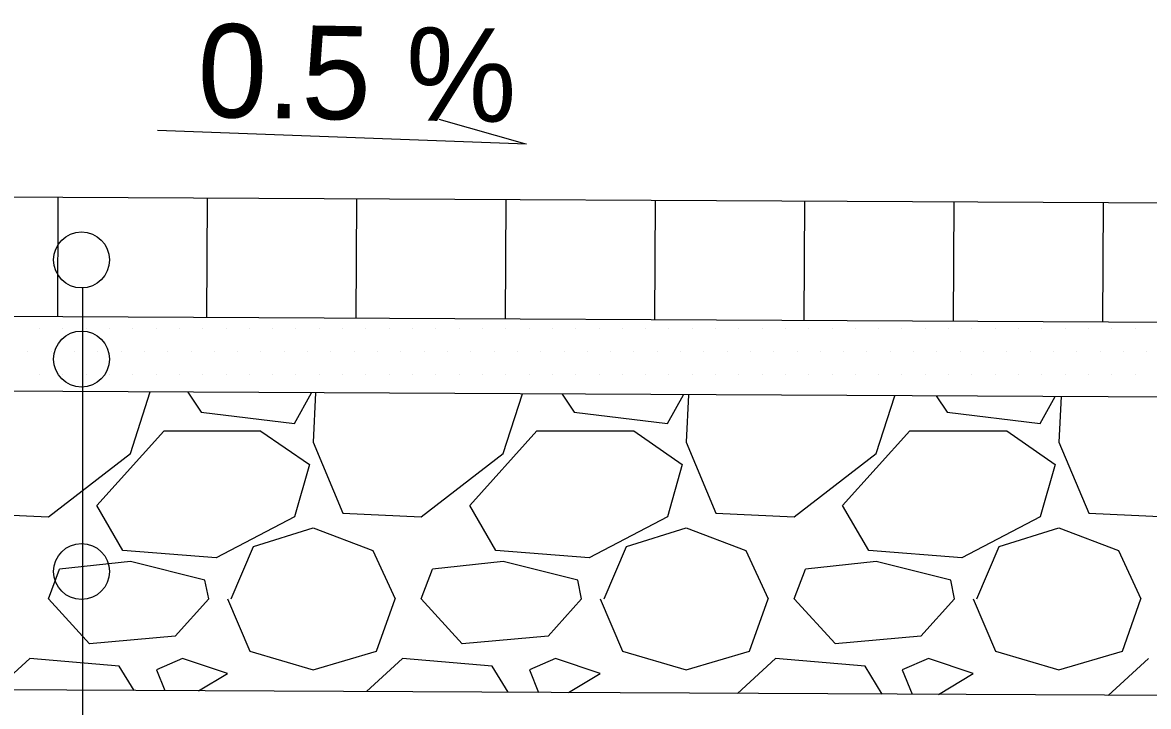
# Model space of a CAD drawing. Extents: x -219625893 to 7498339, y 5791790 to 5792761.
# Drawn here: x 7495217.89 to 7495232.98, y 5791866.28 to 5791875.44 of the extents above; entities that cross this region are included whole.
import ezdxf

# ---------------------------------------------------------------- set-up
doc = ezdxf.new("R2010")
doc.units = 0
for name, color, linetype in [('D_kons_wyp_podsypka_cem-piask', 7, 'Continuous'), ('D_kons_wyp_pospolka', 7, 'Continuous'), ('D_robocze_1', 7, 'Continuous'), ('Level 10', 7, 'Continuous'), ('wymiary', 7, 'Continuous')]:
    doc.layers.add(name, color=color, linetype=linetype)

msp = doc.modelspace()

# ---------------------------------------------------------------- linework, layer by layer
at = {"layer": 'D_kons_wyp_podsypka_cem-piask'}
for p, q in [((7495218.115, 5791871.343), (7495218.115, 5791871.343)), ((7495218.427, 5791871.343), (7495218.427, 5791871.343)), ((7495218.74, 5791871.343), (7495218.74, 5791871.343)), ((7495219.052, 5791871.343), (7495219.052, 5791871.343)), ((7495219.365, 5791871.343), (7495219.365, 5791871.343)), ((7495219.677, 5791871.343), (7495219.677, 5791871.343)), ((7495219.99, 5791871.343), (7495219.99, 5791871.343)), ((7495220.302, 5791871.343), (7495220.302, 5791871.343)), ((7495220.615, 5791871.343), (7495220.615, 5791871.343)), ((7495220.927, 5791871.343), (7495220.927, 5791871.343)), ((7495221.24, 5791871.343), (7495221.24, 5791871.343)), ((7495221.552, 5791871.343), (7495221.552, 5791871.343)), ((7495221.865, 5791871.343), (7495221.865, 5791871.343)), ((7495222.177, 5791871.343), (7495222.177, 5791871.343)), ((7495222.49, 5791871.343), (7495222.49, 5791871.343)), ((7495222.802, 5791871.343), (7495222.802, 5791871.343)), ((7495223.115, 5791871.343), (7495223.115, 5791871.343)), ((7495223.427, 5791871.343), (7495223.427, 5791871.343)), ((7495223.74, 5791871.343), (7495223.74, 5791871.343)), ((7495224.052, 5791871.343), (7495224.052, 5791871.343)), ((7495224.365, 5791871.343), (7495224.365, 5791871.343)), ((7495224.677, 5791871.343), (7495224.677, 5791871.343)), ((7495224.99, 5791871.343), (7495224.99, 5791871.343)), ((7495225.302, 5791871.343), (7495225.302, 5791871.343)), ((7495225.615, 5791871.343), (7495225.615, 5791871.343)), ((7495225.927, 5791871.343), (7495225.927, 5791871.343)), ((7495226.24, 5791871.343), (7495226.24, 5791871.343)), ((7495226.552, 5791871.343), (7495226.552, 5791871.343)), ((7495226.865, 5791871.343), (7495226.865, 5791871.343)), ((7495227.177, 5791871.343), (7495227.177, 5791871.343)), ((7495227.49, 5791871.343), (7495227.49, 5791871.343)), ((7495227.802, 5791871.343), (7495227.802, 5791871.343)), ((7495228.115, 5791871.343), (7495228.115, 5791871.343)), ((7495228.427, 5791871.343), (7495228.427, 5791871.343)), ((7495228.74, 5791871.343), (7495228.74, 5791871.343)), ((7495229.052, 5791871.343), (7495229.052, 5791871.343)), ((7495229.365, 5791871.343), (7495229.365, 5791871.343)), ((7495229.677, 5791871.343), (7495229.677, 5791871.343)), ((7495229.99, 5791871.343), (7495229.99, 5791871.343)), ((7495230.302, 5791871.343), (7495230.302, 5791871.343)), ((7495230.615, 5791871.343), (7495230.615, 5791871.343)), ((7495230.927, 5791871.343), (7495230.927, 5791871.343)), ((7495231.24, 5791871.343), (7495231.24, 5791871.343)), ((7495231.552, 5791871.343), (7495231.552, 5791871.343)), ((7495231.865, 5791871.343), (7495231.865, 5791871.343)), ((7495232.177, 5791871.343), (7495232.177, 5791871.343)), ((7495232.49, 5791871.343), (7495232.49, 5791871.343)), ((7495232.802, 5791871.343), (7495232.802, 5791871.343)), ((7495217.958, 5791871.031), (7495217.958, 5791871.031)), ((7495218.271, 5791871.031), (7495218.271, 5791871.031)), ((7495218.583, 5791871.031), (7495218.583, 5791871.031)), ((7495218.896, 5791871.031), (7495218.896, 5791871.031)), ((7495219.208, 5791871.031), (7495219.208, 5791871.031)), ((7495219.521, 5791871.031), (7495219.521, 5791871.031)), ((7495219.833, 5791871.031), (7495219.833, 5791871.031)), ((7495220.146, 5791871.031), (7495220.146, 5791871.031)), ((7495220.458, 5791871.031), (7495220.458, 5791871.031)), ((7495220.771, 5791871.031), (7495220.771, 5791871.031)), ((7495221.083, 5791871.031), (7495221.083, 5791871.031)), ((7495221.396, 5791871.031), (7495221.396, 5791871.031)), ((7495221.708, 5791871.031), (7495221.708, 5791871.031)), ((7495222.021, 5791871.031), (7495222.021, 5791871.031)), ((7495222.333, 5791871.031), (7495222.333, 5791871.031)), ((7495222.646, 5791871.031), (7495222.646, 5791871.031)), ((7495222.958, 5791871.031), (7495222.958, 5791871.031)), ((7495223.271, 5791871.031), (7495223.271, 5791871.031)), ((7495223.583, 5791871.031), (7495223.583, 5791871.031)), ((7495223.896, 5791871.031), (7495223.896, 5791871.031)), ((7495224.208, 5791871.031), (7495224.208, 5791871.031)), ((7495224.521, 5791871.031), (7495224.521, 5791871.031)), ((7495224.833, 5791871.031), (7495224.833, 5791871.031)), ((7495225.146, 5791871.031), (7495225.146, 5791871.031)), ((7495225.458, 5791871.031), (7495225.458, 5791871.031)), ((7495225.771, 5791871.031), (7495225.771, 5791871.031)), ((7495226.083, 5791871.031), (7495226.083, 5791871.031)), ((7495226.396, 5791871.031), (7495226.396, 5791871.031)), ((7495226.708, 5791871.031), (7495226.708, 5791871.031)), ((7495227.021, 5791871.031), (7495227.021, 5791871.031)), ((7495227.333, 5791871.031), (7495227.333, 5791871.031)), ((7495227.646, 5791871.031), (7495227.646, 5791871.031)), ((7495227.958, 5791871.031), (7495227.958, 5791871.031)), ((7495228.271, 5791871.031), (7495228.271, 5791871.031)), ((7495228.583, 5791871.031), (7495228.583, 5791871.031)), ((7495228.896, 5791871.031), (7495228.896, 5791871.031)), ((7495229.208, 5791871.031), (7495229.208, 5791871.031)), ((7495229.521, 5791871.031), (7495229.521, 5791871.031)), ((7495229.833, 5791871.031), (7495229.833, 5791871.031)), ((7495230.146, 5791871.031), (7495230.146, 5791871.031)), ((7495230.458, 5791871.031), (7495230.458, 5791871.031)), ((7495230.771, 5791871.031), (7495230.771, 5791871.031)), ((7495231.083, 5791871.031), (7495231.083, 5791871.031)), ((7495231.396, 5791871.031), (7495231.396, 5791871.031)), ((7495231.708, 5791871.031), (7495231.708, 5791871.031)), ((7495232.021, 5791871.031), (7495232.021, 5791871.031)), ((7495232.333, 5791871.031), (7495232.333, 5791871.031)), ((7495232.646, 5791871.031), (7495232.646, 5791871.031)), ((7495232.958, 5791871.031), (7495232.958, 5791871.031)), ((7495218.115, 5791870.718), (7495218.115, 5791870.718)), ((7495218.427, 5791870.718), (7495218.427, 5791870.718)), ((7495218.74, 5791870.718), (7495218.74, 5791870.718)), ((7495219.052, 5791870.718), (7495219.052, 5791870.718)), ((7495219.365, 5791870.718), (7495219.365, 5791870.718)), ((7495219.677, 5791870.718), (7495219.677, 5791870.718)), ((7495219.99, 5791870.718), (7495219.99, 5791870.718)), ((7495220.302, 5791870.718), (7495220.302, 5791870.718)), ((7495220.615, 5791870.718), (7495220.615, 5791870.718)), ((7495220.927, 5791870.718), (7495220.927, 5791870.718)), ((7495221.24, 5791870.718), (7495221.24, 5791870.718)), ((7495221.552, 5791870.718), (7495221.552, 5791870.718)), ((7495221.865, 5791870.718), (7495221.865, 5791870.718)), ((7495222.177, 5791870.718), (7495222.177, 5791870.718)), ((7495222.49, 5791870.718), (7495222.49, 5791870.718)), ((7495222.802, 5791870.718), (7495222.802, 5791870.718)), ((7495223.115, 5791870.718), (7495223.115, 5791870.718)), ((7495223.427, 5791870.718), (7495223.427, 5791870.718)), ((7495223.74, 5791870.718), (7495223.74, 5791870.718)), ((7495224.052, 5791870.718), (7495224.052, 5791870.718)), ((7495224.365, 5791870.718), (7495224.365, 5791870.718)), ((7495224.677, 5791870.718), (7495224.677, 5791870.718)), ((7495224.99, 5791870.718), (7495224.99, 5791870.718)), ((7495225.302, 5791870.718), (7495225.302, 5791870.718)), ((7495225.615, 5791870.718), (7495225.615, 5791870.718)), ((7495225.927, 5791870.718), (7495225.927, 5791870.718)), ((7495226.24, 5791870.718), (7495226.24, 5791870.718)), ((7495226.552, 5791870.718), (7495226.552, 5791870.718)), ((7495226.865, 5791870.718), (7495226.865, 5791870.718)), ((7495227.177, 5791870.718), (7495227.177, 5791870.718)), ((7495227.49, 5791870.718), (7495227.49, 5791870.718)), ((7495227.802, 5791870.718), (7495227.802, 5791870.718)), ((7495228.115, 5791870.718), (7495228.115, 5791870.718)), ((7495228.427, 5791870.718), (7495228.427, 5791870.718)), ((7495228.74, 5791870.718), (7495228.74, 5791870.718)), ((7495229.052, 5791870.718), (7495229.052, 5791870.718)), ((7495229.365, 5791870.718), (7495229.365, 5791870.718)), ((7495229.677, 5791870.718), (7495229.677, 5791870.718)), ((7495229.99, 5791870.718), (7495229.99, 5791870.718)), ((7495230.302, 5791870.718), (7495230.302, 5791870.718)), ((7495230.615, 5791870.718), (7495230.615, 5791870.718)), ((7495230.927, 5791870.718), (7495230.927, 5791870.718)), ((7495231.24, 5791870.718), (7495231.24, 5791870.718)), ((7495231.552, 5791870.718), (7495231.552, 5791870.718)), ((7495231.865, 5791870.718), (7495231.865, 5791870.718)), ((7495232.177, 5791870.718), (7495232.177, 5791870.718)), ((7495232.49, 5791870.718), (7495232.49, 5791870.718)), ((7495232.802, 5791870.718), (7495232.802, 5791870.718))]:
    msp.add_line(p, q, dxfattribs=at)
at = {"layer": 'D_kons_wyp_pospolka'}
for p, q in [((7495219.332, 5791869.667), (7495219.596, 5791870.489)), ((7495220.103, 5791870.486), (7495220.282, 5791870.217)), ((7495221.532, 5791870.067), (7495221.761, 5791870.478)), ((7495221.814, 5791870.478), (7495221.782, 5791869.817)), ((7495224.332, 5791869.667), (7495224.588, 5791870.464)), ((7495225.119, 5791870.461), (7495225.282, 5791870.217)), ((7495226.532, 5791870.067), (7495226.747, 5791870.453)), ((7495226.813, 5791870.453), (7495226.782, 5791869.817)), ((7495229.332, 5791869.667), (7495229.58, 5791870.439)), ((7495230.136, 5791870.436), (7495230.282, 5791870.217)), ((7495231.532, 5791870.067), (7495231.733, 5791870.428)), ((7495231.811, 5791870.428), (7495231.782, 5791869.817)), ((7495220.282, 5791870.217), (7495221.532, 5791870.067)), ((7495225.282, 5791870.217), (7495226.532, 5791870.067)), ((7495230.282, 5791870.217), (7495231.532, 5791870.067)), ((7495218.882, 5791868.966), (7495219.782, 5791869.966)), ((7495219.782, 5791869.967), (7495221.082, 5791869.967)), ((7495221.082, 5791869.966), (7495221.732, 5791869.516)), ((7495223.882, 5791868.967), (7495224.782, 5791869.967)), ((7495224.782, 5791869.967), (7495226.082, 5791869.967)), ((7495226.082, 5791869.967), (7495226.732, 5791869.517)), ((7495228.882, 5791868.967), (7495229.782, 5791869.967)), ((7495229.782, 5791869.967), (7495231.082, 5791869.967)), ((7495231.082, 5791869.967), (7495231.732, 5791869.517)), ((7495221.782, 5791869.817), (7495222.182, 5791868.867)), ((7495226.782, 5791869.817), (7495227.182, 5791868.867)), ((7495231.782, 5791869.817), (7495232.182, 5791868.867)), ((7495218.232, 5791868.817), (7495219.332, 5791869.667)), ((7495223.232, 5791868.817), (7495224.332, 5791869.667)), ((7495228.232, 5791868.816), (7495229.332, 5791869.666)), ((7495221.732, 5791869.517), (7495221.532, 5791868.817)), ((7495226.732, 5791869.517), (7495226.532, 5791868.817)), ((7495231.732, 5791869.517), (7495231.532, 5791868.817)), ((7495219.232, 5791868.367), (7495218.882, 5791868.967)), ((7495224.232, 5791868.367), (7495223.882, 5791868.967)), ((7495229.232, 5791868.367), (7495228.882, 5791868.966)), ((7495217.182, 5791868.867), (7495218.232, 5791868.817)), ((7495221.532, 5791868.816), (7495220.482, 5791868.266)), ((7495222.182, 5791868.867), (7495223.232, 5791868.817)), ((7495226.532, 5791868.817), (7495225.482, 5791868.267)), ((7495227.182, 5791868.867), (7495228.232, 5791868.817)), ((7495231.532, 5791868.817), (7495230.482, 5791868.267)), ((7495232.182, 5791868.867), (7495233.232, 5791868.817)), ((7495220.982, 5791868.417), (7495221.782, 5791868.667)), ((7495221.782, 5791868.667), (7495222.582, 5791868.367)), ((7495225.982, 5791868.417), (7495226.782, 5791868.667)), ((7495226.782, 5791868.667), (7495227.582, 5791868.367)), ((7495230.982, 5791868.417), (7495231.782, 5791868.667)), ((7495231.782, 5791868.667), (7495232.582, 5791868.367)), ((7495220.482, 5791868.267), (7495219.232, 5791868.367)), ((7495220.682, 5791867.717), (7495220.982, 5791868.417)), ((7495222.582, 5791868.367), (7495222.882, 5791867.717)), ((7495225.482, 5791868.267), (7495224.232, 5791868.367)), ((7495225.682, 5791867.717), (7495225.982, 5791868.417)), ((7495227.582, 5791868.367), (7495227.882, 5791867.717)), ((7495230.482, 5791868.267), (7495229.232, 5791868.367)), ((7495230.682, 5791867.717), (7495230.982, 5791868.417)), ((7495232.582, 5791868.367), (7495232.882, 5791867.717)), ((7495219.332, 5791868.217), (7495218.382, 5791868.117)), ((7495220.332, 5791867.967), (7495219.332, 5791868.217)), ((7495224.332, 5791868.217), (7495223.382, 5791868.117)), ((7495225.332, 5791867.967), (7495224.332, 5791868.217)), ((7495229.332, 5791868.217), (7495228.382, 5791868.117)), ((7495230.332, 5791867.967), (7495229.332, 5791868.217)), ((7495218.232, 5791867.717), (7495218.382, 5791868.117)), ((7495223.232, 5791867.717), (7495223.382, 5791868.117)), ((7495228.232, 5791867.717), (7495228.382, 5791868.117)), ((7495220.382, 5791867.717), (7495220.332, 5791867.967)), ((7495225.382, 5791867.717), (7495225.332, 5791867.967)), ((7495230.382, 5791867.717), (7495230.332, 5791867.966)), ((7495218.782, 5791867.116), (7495218.232, 5791867.716)), ((7495220.382, 5791867.717), (7495219.932, 5791867.217)), ((7495220.632, 5791867.717), (7495220.932, 5791867.017)), ((7495222.632, 5791867.017), (7495222.882, 5791867.717)), ((7495223.782, 5791867.116), (7495223.232, 5791867.716)), ((7495225.382, 5791867.717), (7495224.932, 5791867.217)), ((7495225.632, 5791867.717), (7495225.932, 5791867.017)), ((7495227.632, 5791867.017), (7495227.882, 5791867.717)), ((7495228.782, 5791867.117), (7495228.232, 5791867.717)), ((7495230.382, 5791867.717), (7495229.932, 5791867.217)), ((7495230.632, 5791867.717), (7495230.932, 5791867.017)), ((7495232.632, 5791867.017), (7495232.882, 5791867.717)), ((7495219.932, 5791867.216), (7495218.782, 5791867.116)), ((7495224.932, 5791867.216), (7495223.782, 5791867.116)), ((7495229.932, 5791867.216), (7495228.782, 5791867.116)), ((7495220.932, 5791867.017), (7495221.782, 5791866.767)), ((7495221.782, 5791866.767), (7495222.632, 5791867.017)), ((7495225.932, 5791867.017), (7495226.782, 5791866.767)), ((7495226.782, 5791866.767), (7495227.632, 5791867.017)), ((7495230.932, 5791867.017), (7495231.782, 5791866.767)), ((7495231.782, 5791866.767), (7495232.632, 5791867.017)), ((7495217.982, 5791866.917), (7495217.525, 5791866.499)), ((7495219.182, 5791866.817), (7495217.982, 5791866.917)), ((7495219.382, 5791866.49), (7495219.182, 5791866.816)), ((7495220.032, 5791866.917), (7495219.682, 5791866.767)), ((7495220.632, 5791866.717), (7495220.032, 5791866.917)), ((7495222.982, 5791866.917), (7495222.498, 5791866.474)), ((7495224.182, 5791866.817), (7495222.982, 5791866.917)), ((7495224.397, 5791866.465), (7495224.182, 5791866.817)), ((7495225.032, 5791866.917), (7495224.682, 5791866.767)), ((7495225.632, 5791866.717), (7495225.032, 5791866.917)), ((7495227.982, 5791866.917), (7495227.471, 5791866.449)), ((7495229.182, 5791866.817), (7495227.982, 5791866.917)), ((7495229.413, 5791866.44), (7495229.182, 5791866.817)), ((7495230.032, 5791866.917), (7495229.682, 5791866.767)), ((7495230.632, 5791866.717), (7495230.032, 5791866.917)), ((7495232.982, 5791866.917), (7495232.443, 5791866.424)), ((7495219.682, 5791866.767), (7495219.794, 5791866.488)), ((7495220.247, 5791866.485), (7495220.632, 5791866.717)), ((7495224.682, 5791866.767), (7495224.804, 5791866.463)), ((7495225.206, 5791866.461), (7495225.632, 5791866.717)), ((7495229.682, 5791866.767), (7495229.814, 5791866.438)), ((7495230.165, 5791866.436), (7495230.632, 5791866.717))]:
    msp.add_line(p, q, dxfattribs=at)
at = {"layer": 'D_robocze_1'}
msp.add_line((7495218.688, 5791871.883), (7495218.688, 5791837.19), dxfattribs=at)
at = {"layer": 'Level 10'}
for p, q in [((7495246.391, 5791872.955), (7495198.458, 5791873.194)), ((7495218.357, 5791871.495), (7495218.365, 5791873.095)), ((7495220.359, 5791871.485), (7495220.367, 5791873.085)), ((7495222.361, 5791871.475), (7495222.369, 5791873.075)), ((7495224.363, 5791871.465), (7495224.371, 5791873.065)), ((7495226.364, 5791871.455), (7495226.372, 5791873.055)), ((7495228.366, 5791871.445), (7495228.374, 5791873.045)), ((7495230.368, 5791871.435), (7495230.376, 5791873.035)), ((7495232.37, 5791871.425), (7495232.378, 5791873.025)), ((7495246.391, 5791871.355), (7495198.45, 5791871.594))]:
    msp.add_line(p, q, dxfattribs=at)
at = {"layer": 'wymiary'}
for p, q in [((7495224.62, 5791873.812), (7495223.472, 5791874.141)), ((7495224.645, 5791873.811), (7495219.697, 5791873.991)), ((7495246.386, 5791870.355), (7495198.445, 5791870.594)), ((7495246.366, 5791866.355), (7495199.458, 5791866.589))]:
    msp.add_line(p, q, dxfattribs=at)
for centre in [(7495218.677, 5791872.258), (7495218.677, 5791870.93), (7495218.677, 5791868.084)]:
    msp.add_circle(centre, 0.375, dxfattribs=at)

# ---------------------------------------------------------------- texts
msp.add_text('0.5 %', height=1.2509, rotation=359.0545, dxfattribs=at).set_placement((7495220.224, 5791874.175))

doc.saveas('drawing.dxf')
